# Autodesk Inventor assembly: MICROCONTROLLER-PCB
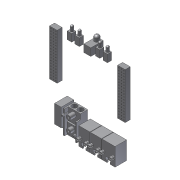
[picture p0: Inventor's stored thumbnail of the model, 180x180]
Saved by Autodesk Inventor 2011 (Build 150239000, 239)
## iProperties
Created: 2010-06
Part Number: MICROCONTROLLER-PCB
Document SubType Name: Assembly
Designer: kurdi
Author: kurdi
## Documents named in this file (6)
- D:\@VEX\BZ-Parts Kit\Logic\MICROCONTROLLER-PCB.iam
- D:\@VEX\BZ-Parts Kit\Imported Components\V23EX-MICROCONTROLLER\MICROCONTROLLER-PCB-PIN4.ipt
- D:\@VEX\BZ-Parts Kit\Imported Components\V23EX-MICROCONTROLLER\MICROCONTROLLER-PCB-PIN6.ipt
- D:\@VEX\BZ-Parts Kit\Imported Components\V23EX-MICROCONTROLLER\MICROCONTROLLER-PCB-BASE.ipt
- D:\@VEX\BZ-Parts Kit\Imported Components\V23EX-MICROCONTROLLER\MICROCONTROLLER-PCB-POWER.ipt
- D:\@VEX\BZ-Parts Kit\Imported Components\V23EX-MICROCONTROLLER\MICROCONTROLLER-PCB-SWITCH.ipt
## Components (6 placed, 5 different names)
1. MICROCONTROLLER-PCB-PIN4:1
2. MICROCONTROLLER-PCB-PIN6:1
3. MICROCONTROLLER-PCB-BASE:1
4. MICROCONTROLLER-PCB-POWER:1
5. MICROCONTROLLER-PCB-PIN4:2
6. MICROCONTROLLER-PCB-SWITCH:1
